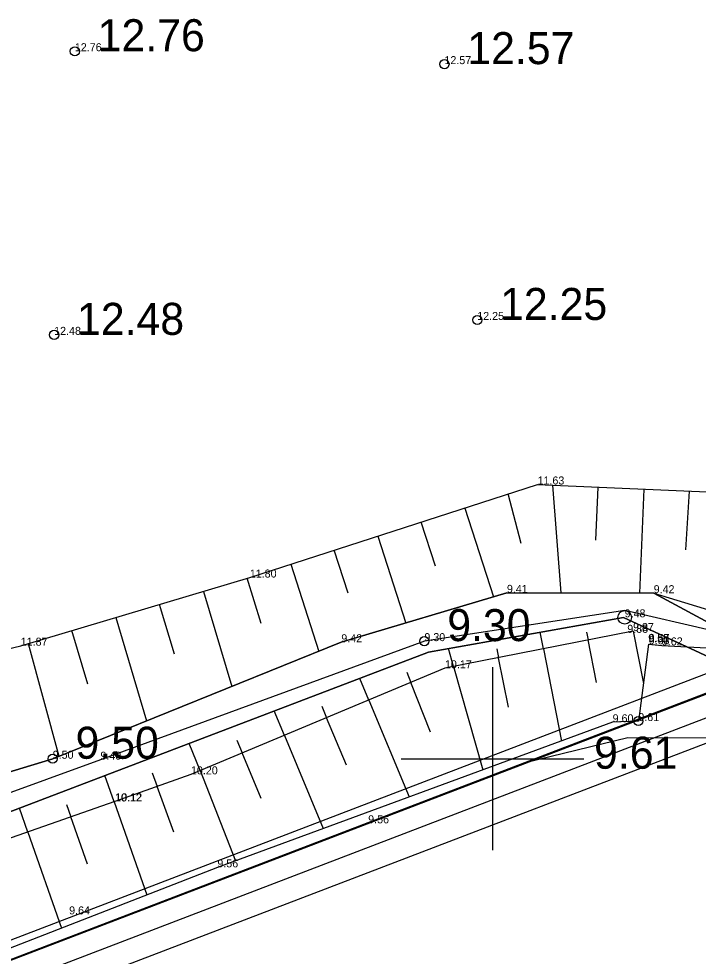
# Model space of a CAD drawing. Extents: x 433497 to 434382, y 6534486 to 6534993.
# Drawn here: x 433879.28 to 433909, y 6534891.36 to 6534932.36 of the extents above; entities that cross this region are included whole.
import ezdxf

# ---------------------------------------------------------------- set-up
doc = ezdxf.new("R2010")
doc.units = 0
for name, color, linetype in [('Default', 7, 'Continuous'), ('kataster', 7, 'Continuous'), ('KORGUS-EH2000', 7, 'Continuous'), ('Lamami horisontaal', 7, 'Continuous'), ('MOOTKORG-EH2000', 7, 'Continuous'), ('PIIR', 7, 'Continuous'), ('RELJEEF', 7, 'Continuous'), ('VEEKOGU', 7, 'Continuous'), ('VORK', 7, 'Continuous')]:
    doc.layers.add(name, color=color, linetype=linetype)

msp = doc.modelspace()

# ---------------------------------------------------------------- linework, layer by layer
at = {"layer": 'Default'}
msp.add_lwpolyline([(433617.12, 6534791.025), (433632.75, 6534606.045), (434137.38, 6534796.515), (434127.69, 6534855.6), (433968.21, 6534911.925), (433942.38, 6534904.035), (433920.99, 6534907.275)], close=True, dxfattribs=at)
msp.add_lwpolyline([(433617.12, 6534791.025), (433632.75, 6534606.045), (434137.38, 6534796.515), (434127.69, 6534855.6), (433968.21, 6534911.925), (433942.38, 6534904.035), (433920.99, 6534907.275)], close=True, dxfattribs=at)
msp.add_lwpolyline([(433617.12, 6534791.025), (433632.75, 6534606.045), (434137.38, 6534796.515), (434127.69, 6534855.6), (433968.21, 6534911.925), (433942.38, 6534904.035), (433920.99, 6534907.275)], close=True, dxfattribs=at)
at = {"layer": 'kataster'}
msp.add_lwpolyline([(433617.102, 6534791.002), (433632.769, 6534606.029), (434137.446, 6534796.469), (434127.827, 6534855.589), (433950.026, 6534918.39)], close=True, dxfattribs=at)
at = {"layer": 'KORGUS-EH2000'}
for centre in [(433881.73, 6534930.94), (433897.899, 6534930.376), (433899.334, 6534919.189), (433880.825, 6534918.537), (433897.022, 6534905.145), (433906.382, 6534901.649), (433880.761, 6534900.001)]:
    msp.add_circle(centre, 0.2, dxfattribs=at)
at = {"layer": 'Lamami horisontaal'}
msp.add_lwpolyline([(433901.435, 6534899.835), (433905.917, 6534900.93), (433913.287, 6534900.915), (433920.411, 6534899.023), (433927.288, 6534895.254), (433957.622, 6534874.107)], dxfattribs=at)
at = {"layer": 'PIIR'}
for points in [[(433632.021, 6534604.835), (434138.248, 6534795.936), (434128.468, 6534856.135), (433968.226, 6534912.818), (433942.33, 6534904.85), (433920.952, 6534908.165), (433616.327, 6534791.524), (433632.021, 6534604.835)], [(433632.732, 6534605.959), (434137.353, 6534796.454), (434127.754, 6534855.539), (433968.208, 6534911.976), (433942.39, 6534904.031), (433921.04, 6534907.341), (433617.174, 6534790.992), (433632.732, 6534605.959)]]:
    msp.add_lwpolyline(points, dxfattribs=at)
for points in [[(433618.234, 6534790.327), (433921.149, 6534906.313), (433942.464, 6534903.008), (433968.187, 6534910.923), (434126.862, 6534854.794), (434136.235, 6534797.101), (433633.617, 6534607.362)], [(433619.24, 6534789.695), (433634.52, 6534608.851), (434135.141, 6534797.808), (434125.908, 6534854.108), (433968.165, 6534909.82), (433942.53, 6534901.99), (433921.212, 6534905.219)], [(433619.24, 6534789.695), (433634.52, 6534608.851), (434135.141, 6534797.808), (434125.908, 6534854.108), (433968.165, 6534909.82), (433942.53, 6534901.99), (433921.212, 6534905.219)]]:
    msp.add_lwpolyline(points, close=True, dxfattribs=at)
at = {"layer": 'RELJEEF'}
for p, q in [((433902.625, 6534911.966), (433902.988, 6534907.25)), ((433904.523, 6534909.563), (433904.623, 6534911.879)), ((433906.621, 6534911.793), (433906.425, 6534907.242)), ((433908.465, 6534909.135), (433908.62, 6534911.707)), ((433901.254, 6534909.417), (433900.691, 6534911.58)), ((433898.788, 6534910.965), (433900.044, 6534907.081)), ((433897.506, 6534908.429), (433896.885, 6534910.35)), ((433894.982, 6534909.735), (433896.209, 6534905.937)), ((433893.686, 6534907.242), (433893.079, 6534909.119)), ((433891.176, 6534908.504), (433892.403, 6534904.698)), ((433889.885, 6534905.911), (433889.272, 6534907.892)), ((433887.355, 6534907.322), (433888.592, 6534903.161)), ((433886.083, 6534904.58), (433885.438, 6534906.752)), ((433883.521, 6534906.182), (433884.866, 6534901.657)), ((433882.303, 6534903.259), (433881.604, 6534905.612)), ((433902.225, 6534904.809), (433902.082, 6534905.534)), ((433904.119, 6534905.542), (433904.187, 6534905.198)), ((433906.149, 6534905.587), (433906.603, 6534903.299)), ((433906.149, 6534905.587), (433906.603, 6534903.299)), ((433904.556, 6534903.336), (433904.187, 6534905.198)), ((433879.687, 6534905.042), (433881.033, 6534900.111)), ((433898.302, 6534904.031), (433898.078, 6534904.82)), ((433900.188, 6534904.801), (433900.264, 6534904.42)), ((433902.225, 6534904.809), (433903.025, 6534900.777)), ((433900.694, 6534902.25), (433900.264, 6534904.42)), ((433898.302, 6534904.031), (433899.583, 6534899.514)), ((433894.588, 6534902.564), (433894.191, 6534903.516)), ((433896.256, 6534903.785), (433896.434, 6534903.335)), ((433897.292, 6534901.162), (433896.434, 6534903.335)), ((433892.532, 6534902.299), (433892.742, 6534901.794)), ((433894.588, 6534902.564), (433896.355, 6534898.33)), ((433890.896, 6534901.024), (433890.451, 6534902.09)), ((433893.609, 6534899.717), (433892.742, 6534901.794)), ((433890.896, 6534901.024), (433892.596, 6534896.951)), ((433887.205, 6534899.483), (433886.737, 6534900.674)), ((433888.816, 6534900.816), (433889.051, 6534900.254)), ((433889.884, 6534898.258), (433889.051, 6534900.254)), ((433885.115, 6534899.382), (433885.329, 6534898.79)), ((433887.205, 6534899.483), (433888.755, 6534895.542)), ((433883.446, 6534898.118), (433883.04, 6534899.265)), ((433886.055, 6534896.791), (433885.329, 6534898.79)), ((433883.446, 6534898.118), (433884.882, 6534894.052)), ((433879.67, 6534896.797), (433879.305, 6534897.841)), ((433881.366, 6534898.006), (433881.558, 6534897.458)), ((433882.282, 6534895.389), (433881.558, 6534897.458)), ((433879.67, 6534896.797), (433881.141, 6534892.594))]:
    msp.add_line(p, q, dxfattribs=at)
for points in [[(433763.585, 6534891.607), (433768.482, 6534879.707), (433779.317, 6534877.624), (433783.641, 6534876.671), (433789.159, 6534878.039), (433798.484, 6534881.14), (433803.042, 6534877.671), (433810.627, 6534877.969), (433823.017, 6534882.312), (433834.298, 6534889.425), (433849.2, 6534895.864), (433854.211, 6534899.146), (433866.477, 6534901.86), (433879.364, 6534904.946), (433889.384, 6534907.925), (433901.971, 6534911.994), (433910.4, 6534911.63), (433916.859, 6534909.226), (433919.332, 6534909.737), (433920.484, 6534910.314), (433922.121, 6534910.322), (433923.615, 6534910.205)], [(433907.052, 6534907.24), (433916.008, 6534904.516), (433917.858, 6534906.468), (433920.952, 6534907.058), (433921.355, 6534906.578), (433918.811, 6534901.575), (433917.104, 6534899.283), (433914.485, 6534891.79), (433912.65, 6534882.047), (433911.296, 6534879.715), (433907.843, 6534872.13), (433899.687, 6534858.873), (433894.244, 6534849.654), (433892.501, 6534844.802)], [(433906.149, 6534905.587), (433897.922, 6534903.956), (433886.809, 6534899.318), (433883.485, 6534898.132), (433864.446, 6534891.471), (433857.552, 6534886.493), (433857.552, 6534886.493), (433849.679, 6534883.381), (433842.481, 6534880.201), (433838.555, 6534878.274), (433829.853, 6534875.521), (433829.557, 6534875.474), (433822.217, 6534876.48)], [(433906.831, 6534905.005), (433906.382, 6534901.649), (433905.256, 6534901.595), (433887.965, 6534895.252), (433868.017, 6534887.484), (433860.753, 6534882.034), (433855.448, 6534875.059), (433841.724, 6534868.496), (433830.76, 6534867.983), (433826.254, 6534869.208), (433822.145, 6534872.793), (433822.217, 6534876.48)]]:
    msp.add_lwpolyline(points, dxfattribs=at)
at = {"layer": 'VEEKOGU'}
for points in [[(433762.728, 6534893.927), (433766.059, 6534880.045), (433768.451, 6534877.273), (433777.011, 6534876.737), (433783.737, 6534875.048), (433789.533, 6534875.633), (433792.948, 6534877.948), (433797.961, 6534878.694), (433803.158, 6534876.065), (433815.183, 6534876.407), (433824.703, 6534879.159), (433850.58, 6534889.135), (433868.878, 6534896.391), (433880.761, 6534900.001), (433893.386, 6534905.095), (433900.632, 6534907.256), (433907.052, 6534907.24), (433915.879, 6534902.485), (433917.357, 6534901.473)], [(433917.357, 6534901.473), (433915.879, 6534902.485), (433907.052, 6534907.24), (433900.632, 6534907.256), (433893.386, 6534905.095), (433880.761, 6534900.001), (433868.878, 6534896.391), (433850.58, 6534889.135), (433824.703, 6534879.159), (433815.183, 6534876.407), (433803.158, 6534876.065), (433797.961, 6534878.694), (433792.948, 6534877.948), (433789.533, 6534875.633), (433783.737, 6534875.048), (433777.011, 6534876.737), (433768.451, 6534877.273), (433766.059, 6534880.045), (433762.728, 6534893.927)], [(433917.729, 6534901.381), (433909.569, 6534905.615), (433905.783, 6534906.485), (433897.022, 6534905.145), (433882.849, 6534899.96), (433864.095, 6534893.13), (433840.653, 6534883.7), (433822.307, 6534877.511)], [(433917.357, 6534901.473), (433910.646, 6534903.91), (433905.733, 6534906.185), (433897.201, 6534904.664), (433864.652, 6534892.255), (433840.997, 6534882.39), (433822.758, 6534877.106), (433813.338, 6534872.69), (433806.812, 6534870.137), (433792.733, 6534866.126), (433778.163, 6534862.151), (433760.314, 6534861.045), (433757.652, 6534861.824), (433749.479, 6534854.726), (433748.765, 6534853.283)], [(433749.479, 6534854.726), (433757.652, 6534861.824), (433760.314, 6534861.045), (433778.163, 6534862.151), (433792.733, 6534866.126), (433806.812, 6534870.137), (433813.338, 6534872.69), (433822.758, 6534877.106), (433840.997, 6534882.39), (433864.652, 6534892.255), (433897.201, 6534904.664), (433905.733, 6534906.185), (433910.646, 6534903.91), (433917.357, 6534901.473)], [(433906.831, 6534905.005), (433907.409, 6534904.959), (433909.363, 6534904.847), (433911.861, 6534900.956), (433917.104, 6534899.283)]]:
    msp.add_lwpolyline(points, dxfattribs=at)
msp.add_circle((433905.783, 6534906.185), 0.3, dxfattribs=at)
at = {"layer": 'VORK'}
for p, q in [((433900, 6534904), (433900, 6534896)), ((433896, 6534900), (433904, 6534900))]:
    msp.add_line(p, q, dxfattribs=at)

# ---------------------------------------------------------------- texts
at = {"layer": 'KORGUS-EH2000'}
for s, p in [('12.76', (433882.73, 6534930.94)), ('12.57', (433898.899, 6534930.376)), ('12.25', (433900.334, 6534919.189)), ('12.48', (433881.825, 6534918.537)), ('9.30', (433898.022, 6534905.145)), ('9.50', (433881.761, 6534900.001)), ('9.61', (433904.445, 6534899.565))]:
    msp.add_text(s, height=1.4, dxfattribs=at).set_placement(p)
at = {"layer": 'MOOTKORG-EH2000'}
for s, p in [('12.76', (433881.73, 6534930.94)), ('12.57', (433897.899, 6534930.376)), ('12.25', (433899.334, 6534919.189)), ('12.48', (433880.825, 6534918.537)), ('11.63', (433901.971, 6534911.994)), ('11.80', (433889.384, 6534907.925)), ('9.41', (433900.632, 6534907.256)), ('9.42', (433907.052, 6534907.24)), ('9.48', (433905.783, 6534906.185)), ('9.87', (433906.149, 6534905.587)), ('9.30', (433897.022, 6534905.145)), ('9.88', (433905.897, 6534905.509)), ('9.57', (433906.835, 6534905.112)), ('11.87', (433879.364, 6534904.946)), ('9.42', (433893.386, 6534905.095)), ('9.58', (433906.812, 6534905.096)), ('9.63', (433906.831, 6534905.005)), ('9.62', (433907.409, 6534904.959)), ('10.17', (433897.922, 6534903.956)), ('9.60', (433905.256, 6534901.595)), ('9.61', (433906.382, 6534901.649)), ('9.50', (433880.761, 6534900.001)), ('9.40', (433882.849, 6534899.96)), ('10.20', (433886.809, 6534899.318)), ('10.12', (433883.485, 6534898.132)), ('10.12', (433883.504, 6534898.142)), ('9.56', (433894.563, 6534897.178)), ('9.56', (433887.965, 6534895.252)), ('9.64', (433881.48, 6534893.195))]:
    msp.add_text(s, height=0.35, dxfattribs=at).set_placement(p)

doc.saveas('drawing.dxf')
